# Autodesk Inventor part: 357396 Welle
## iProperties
Created: 2005-10
Part Number: 357396 Welle
Material: 1.0718
Document SubType Name: Modeling
Designer: I.Baliuc
Manufacturer: Standard
Standards Organization: Custom
Description: Schaltwelle
Cost Center: 2,938 kg
Authority: 374765 mm^3
Density: 7.84 g/cm^3
Title: Schaltwelle
Company: Mayer & Müller AG Schaltgeräte
SaveDate: 2006-10-25
SaveTime: 23:06
TotalMass: 2,938 kg
TotalVolume: 374765 mm^3
Author: T.Messerschmitt
Comments: Trenner 3 - polig Motorantrieb
Revision Number: 357396
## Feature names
1. Extrusion2
2. Extrusion3
3. Extrusion4
4. Extrusion5
5. Extrusion6
6. Extrusion7
7. Extrusion8
8. Fase1 [Chamfer]
9. Extrusion9
10. Extrusion10
11. Fase2 [Chamfer]
12. Extrusion11
13. Extrusion13
14. Fase4 [Chamfer]
